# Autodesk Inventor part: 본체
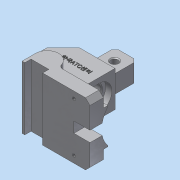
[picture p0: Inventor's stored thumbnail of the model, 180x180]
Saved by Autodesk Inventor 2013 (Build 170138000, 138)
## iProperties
Created: 2016-11
Part Number: 본체
Material: 알루미늄 6061
Document SubType Name: Modeling
Designer: dgall
Density: 1 g/cm^3
Author: dgall
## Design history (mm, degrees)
sketch "스케치1"
  geometry: L1 (0, 0)-(0, 15); L2 (0, 0)-(3, 0); L3 (3, 0)-(3, 7); L4 (3, 7)-(23, 7); L5 (23, 7)-(23, 0); L6 (23, 0)-(76, 0); L7 (76, 0)-(76, 15); L8 (76, 15)-(26, 15); A1 r 13 centre (13, 15) between (26, 15) and (0, 15); 2 further points
  constraints: 16 end point, 4 parallel, 2 perpendicular, 2 point on circle, 1 centre point, 1 coincident, 1 collinear, 1 horizontal alignment, 1 midpoint, 1 point on line, 1 vertical, 1 vertical alignment
  dimensions: "d0" = 13 radius of A1; "d2" = 7 distance of L2.end L3.end; "d3" = 3 distance of L1.start L2.end; "d4" = 20 distance of L3.end L4.end; "d5" = 63 distance from line of L7 A1.centre; "d6" = 15 distance between parallel lines of L6 L8
extrude "돌출1" new body sketch "스케치1" distance "d7" = 70; taper "d8" = 0 deg
node "작업 평면1"
sketch "스케치2"
  geometry: L1 (-14, 12)-(-14, 42); L2 (-14, 42)-(4, 60); L3 (4, 60)-(14, 60); L4 (14, 60)-(14, 90); L5 (14, 90)-(39, 90); L6 (0, 0)-(0, 15) reference; L7 (26, 15)-(76, 15) reference; L8 (76, 15)-(76, 0) reference; L9 (76, 0)-(23, 0) reference; L10 (23, 0)-(23, 7) reference; L11 (23, 7)-(3, 7) reference; L12 (3, 7)-(3, 0) reference; L13 (3, 0)-(0, 0) reference; L14 (39, 90)-(39, 60); L15 (39, 60)-(44, 60); L16 (-14, 12)-(44, 12); L17 (44, 12)-(44, 60); A1 r 13 centre (13, 15) between (26, 15) and (0, 15) reference; 1 further point
  constraints: 18 end point, 3 parallel, 2 perpendicular, 2 vertical
  dimensions: "d9" = 12 distance from line of L13 L1.start; "d12" = 45 deg angle of L3 L2; "d13" = 18 distance from line of L2.end L1; "d17" = 25 distance of L4.end L5.end; "d21" = 90 distance between parallel lines of L9 L5; "d22" = 60 distance between parallel lines of L9 L15; "d23" = 5 distance of L14.end L15.end; "d25" = 90 distance between parallel lines of L8 L1; "d26" = 48 distance between parallel lines of L16 L3; "d97" = 58 distance between parallel lines of L17 L1
extrude "돌출2" join sketch "스케치2" stored distance "d27" = 40; taper "d28" = 0 deg
sketch "스케치3"
  geometry: L1 (0, 30)-(40, 30) reference; L2 (0, 0)-(0, 30) reference; L3 (0, 0)-(40, 0) reference; L4 (40, 30)-(40, 0) reference; L5 (10, 30)-(10, 0); L6 (30, 30)-(30, 0); L7 (30, 0)-(40, 0); L8 (30, 30)-(40, 30); L9 (40, 30)-(40, 0); L10 (10, 30)-(0, 30); L11 (0, 30)-(0, 0); L12 (0, 0)-(10, 0); 1 further point
  constraints: 16 end point, 4 collinear, 4 perpendicular, 4 point on line
  dimensions: "d29" = 10 distance between parallel lines of L5 L11; "d30" = 10 distance between parallel lines of L4 L6
extrude "돌출3" cut sketch "스케치3" distance "d31" = 40; taper "d32" = 0 deg
sketch "스케치4"
  geometry: L1 (15, -15)-(-55, -15) reference; C1 r 10 at (-20, 27); C2 r 14.5 at (-20, 27); 1 further point
  constraints: 2 centre point, 1 coincident, 1 midpoint, 1 vertical alignment
  dimensions: "d35" = 20 diameter of C1; "d37" = 29 diameter of C2; "d38" = 42 distance from line of L1 C1.centre
extrude "돌출4" cut sketch "스케치4" stored distance "d39" = 40; taper "d40" = 0 deg
extrude "돌출5" cut sketch "스케치4" distance "d41" = 7; taper "d42" = 0 deg
chamfer "모따기1" distance "d43" = 1; stored, may be unused: second distance "d44" = 2, angle "d45" = 45 deg
sketch "스케치6"
  geometry: L1 (-25, 30)-(0, 30) reference; L2 (-16, -60)-(37, -60) reference; C1 r 4 at (-12.5, 17); 2 further points
  constraints: 1 centre point, 1 midpoint, 1 vertical alignment
  dimensions: "d48" = 8 diameter of C1; "d50" = 77 distance from line of L2 C1.centre
extrude "돌출6" cut sketch "스케치6" stored distance "d51" = 7; taper "d52" = 0 deg
chamfer "모따기2" distance "d53" = 1; stored, may be unused: second distance "d54" = 2, angle "d55" = 45 deg
sketch "스케치7"
  geometry: L1 (0, 15)-(0, 0) reference; L2 (0, 0)-(-70, 0) reference; L3 (-41, 0)-(-41, 13.627); L4 (-29, 0)-(-29, 13.627); L5 (-41, 0)-(-29, 0); C1 r 14.5 at (-35, 42) reference; A1 r 29 centre (-35, 42) between (-41, 13.627) and (-29, 13.627); 1 further point
  constraints: 6 end point, 2 parallel, 2 perpendicular, 2 point on circle, 2 point on line, 1 centre point, 1 coincident, 1 collinear, 1 midpoint, 1 vertical alignment
  dimensions: "d56" = 12 distance of L3.start L4.start; "d58" = 58 diameter of A1
sketch "스케치8"
  geometry: L1 (0, 0)-(-70, 0) reference; L2 (-15, 15)-(-55, 15) reference; L3 (-15, 60)-(-15, 15) reference; L4 (-55, 60)-(-15, 60) reference; L5 (-55, 15)-(-55, 60) reference; L6 (-55, 20)-(-55, 0); L7 (-55, 20)-(-15, 20); L8 (-15, 20)-(-15, 0); C1 r 14.5 at (-35, 42) reference
  constraints: 6 end point, 3 perpendicular, 2 point on line, 2 vertical alignment
  dimensions: "d59" = 20 distance of L6.start L6.end
extrude "돌출7" join sketch "스케치8" stored distance "d61" = 0; taper "d62" = 0 deg
extrude "돌출8" cut sketch "스케치7" distance "d63" = 18; taper "d64" = 0 deg
chamfer "모따기3" distance "d68" = 4; stored, may be unused: second distance "d69" = 2, angle "d70" = 45 deg
chamfer "모따기4" distance "d71" = 4; stored, may be unused: second distance "d72" = 2, angle "d73" = 45 deg
fillet "모깎기1" dims "d74" = 5
chamfer "모따기5" distance "d75" = 5; stored, may be unused: second distance "d76" = 2, angle "d77" = 45 deg
sketch "스케치10"
  geometry: L1 (0, 15)-(40.708, 15) reference; L2 (45.708, 10)-(45.708, 0) reference; L3 (45.708, -50)-(40.708, -55) reference; L4 (45.708, -40)-(45.708, -50) reference; L5 (45.708, -40)-(0, -40) reference; L6 (0, -55)-(0, -40) reference; L7 (40.708, -55)-(0, -55) reference; L8 (4.708, -10)-(4.708, -30) reference; L9 (4.708, -10)-(-12.292, -10) reference; L10 (-12.292, -30)-(-12.292, -10) reference; L11 (-12.292, -30)-(4.708, -30) reference; L12 (45.708, -38.894)-(27.708, -38.894) reference; L13 (27.708, -38.894)-(27.708, -1.106) reference; L14 (27.708, -1.106)-(45.708, -1.106) reference; L15 (45.708, 0)-(45.708, -1.106) reference; L16 (45.708, 0)-(13.708, 0) reference; L17 (13.708, -40)-(13.708, 0) reference; L18 (45.708, -40)-(13.708, -40) reference; L19 (45.708, -38.894)-(45.708, -40) reference; 3 further points
  dimensions: "d78" = 18 distance from line of L2 point (27.708, 7.5); "d79" = 18 distance from line of point (27.708, -47.5) L4; "d80" = 55 distance of point (27.708, -47.5) point (27.708, 7.5); "d81" = 7.5 distance from line of point (27.708, 7.5) L1
hole "구멍1" sketch "스케치10" at (27.708, 7.5), (27.708, -47.5) diameter "d82" = 3.459; stored, may be unused: countersink angle "d86" = 90 deg, drill point angle "d88" = 118 deg; dims "d83" = 6, "d84" = 4, "d85" = 2, "d87" = 8
sketch "스케치11"
  geometry: L1 (44, 20)-(44, 60) reference; L2 (44, 60)-(4, 60) reference; 2 further points
  constraints: 1 other
  dimensions: "d89" = 18 distance from line of point (19, 42) L2; "d90" = 25 distance from line of L1 point (19, 42)
feature "엠보싱1" sketch "스케치11" dims "d0" = 13, "d2" = 7, "d3" = 3, "d4" = 20, "d5" = 63, "d6" = 15, "d91" = 0.5, "d92" = 0
fillet "모깎기2" dims "d93" = 3
fillet "모깎기3" dims "d94" = 3
sketch "스케치12"
  geometry: L1 (0, 0)-(0, 7) reference; L2 (20, 0)-(0, 0) reference; L3 (20, 7)-(20, 0) reference; L4 (0, 7)-(20, 7) reference; L5 (0, 0)-(0, 7); L6 (20, 7)-(20, 0); L7 (0, 0)-(20, 0); L8 (20, 0)-(20, 7); L9 (0, 7)-(20, 7); L10 (20, 7)-(20, 0); L11 (20, 7)-(20, 0); L12 (20, 7)-(20, 0); L13 (20, 0)-(20, 7); 1 further point
  constraints: 18 end point, 9 collinear
extrude "돌출9" cut sketch "스케치12" stored distance "d95" = 18; taper "d96" = 0 deg
node "솔리드1"
node "투영된 루프1"
node "투영된 루프2"
node "투영된 루프3"
node "투영된 루프4"
node "투영된 루프5"
